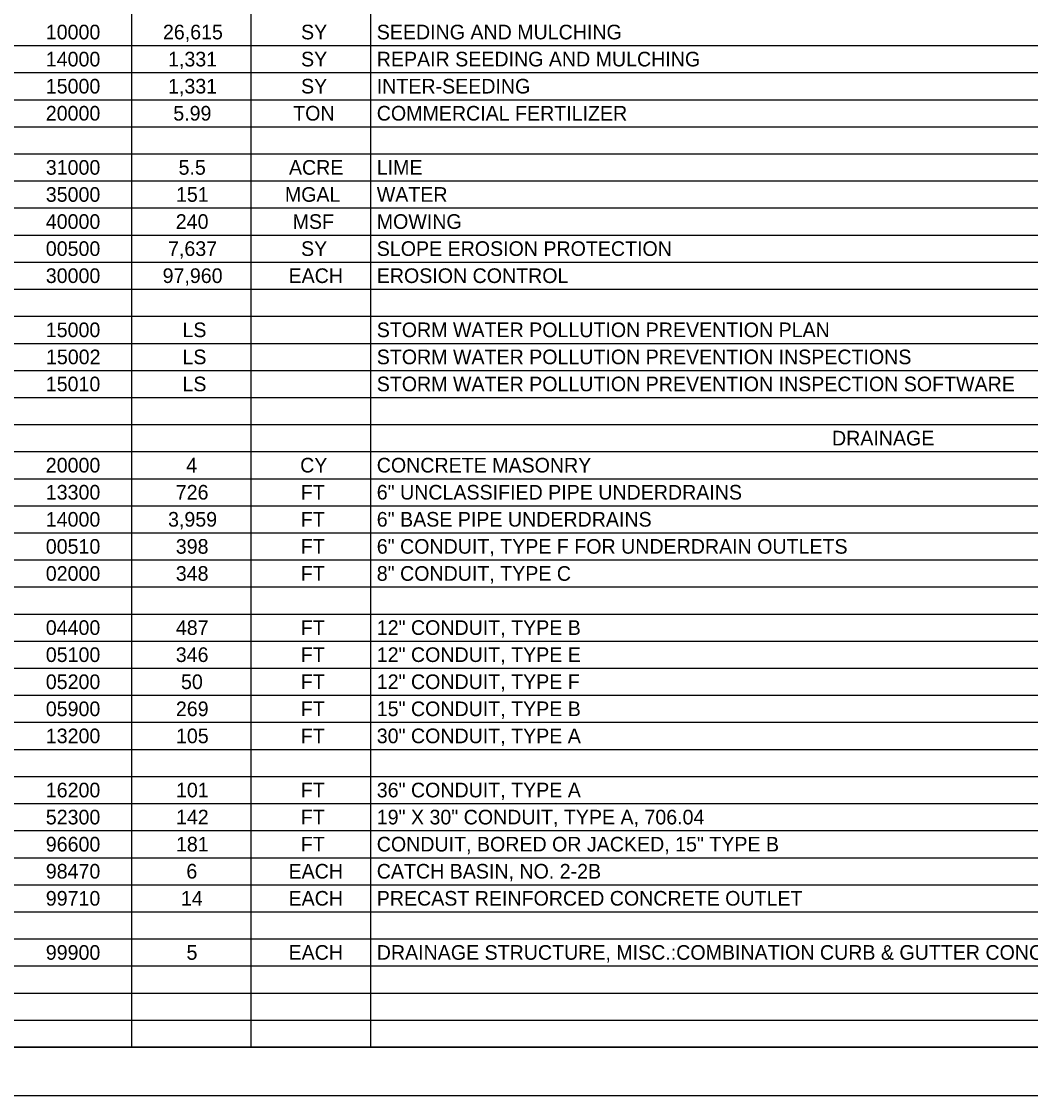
# Model space of a CAD drawing. Extents: x 0 to 34, y 0 to 22.
# Drawn here: x 16.9 to 27.33, y 0 to 11.11 of the extents above; entities that cross this region are included whole.
import ezdxf

# ---------------------------------------------------------------- set-up
doc = ezdxf.new("R2010")
doc.units = 0
for name, color, linetype in [('SH_Border', 7, 'Continuous'), ('SH_Cut_Line', 7, 'Continuous'), ('SH_Text', 7, 'Continuous')]:
    doc.layers.add(name, color=color, linetype=linetype)

msp = doc.modelspace()

# ---------------------------------------------------------------- linework, layer by layer
at = {"layer": 'SH_Border'}
msp.add_lwpolyline([(1.5, 21.5), (33.5, 21.5), (33.5, 0.5), (1.5, 0.5)], close=True, dxfattribs=at)
at = {"layer": 'SH_Cut_Line'}
msp.add_lwpolyline([(0, 0), (34, 0), (34, 22), (0, 22)], close=True, dxfattribs=at)
at = {"layer": 'SH_Text'}
for p, q in [((18.035, 21.5), (18.035, 0.5)), ((19.27, 21.5), (19.27, 0.5)), ((20.505, 21.5), (20.505, 0.5)), ((1.5, 10.86), (32, 10.86)), ((1.5, 10.58), (32, 10.58)), ((1.5, 10.3), (32, 10.3)), ((1.5, 10.02), (32, 10.02)), ((1.5, 9.74), (32, 9.74)), ((1.5, 9.46), (32, 9.46)), ((1.5, 9.18), (32, 9.18)), ((1.5, 8.9), (32, 8.9)), ((1.5, 8.62), (32, 8.62)), ((1.5, 8.34), (32, 8.34)), ((1.5, 8.06), (32, 8.06)), ((1.5, 7.78), (32, 7.78)), ((1.5, 7.5), (32, 7.5)), ((1.5, 7.22), (32, 7.22)), ((1.5, 6.94), (32, 6.94)), ((1.5, 6.66), (32, 6.66)), ((1.5, 6.38), (32, 6.38)), ((1.5, 6.1), (32, 6.1)), ((1.5, 5.82), (32, 5.82)), ((1.5, 5.54), (32, 5.54)), ((1.5, 5.26), (32, 5.26)), ((1.5, 4.98), (32, 4.98)), ((1.5, 4.7), (32, 4.7)), ((1.5, 4.42), (32, 4.42)), ((1.5, 4.14), (32, 4.14)), ((1.5, 3.86), (32, 3.86)), ((1.5, 3.58), (32, 3.58)), ((1.5, 3.3), (32, 3.3)), ((1.5, 3.02), (32, 3.02)), ((1.5, 2.74), (32, 2.74)), ((1.5, 2.46), (32, 2.46)), ((1.5, 2.18), (32, 2.18)), ((1.5, 1.9), (32, 1.9)), ((1.5, 1.62), (32, 1.62)), ((1.5, 1.34), (32, 1.34)), ((1.5, 1.06), (32, 1.06)), ((1.5, 0.78), (32, 0.78)), ((1.5, 0.5), (32, 0.5))]:
    msp.add_line(p, q, dxfattribs=at)

# ---------------------------------------------------------------- texts
for s, height, p in [('10000', 0.1515, (17.149, 10.924)), ('26,615', 0.1515, (18.36, 10.924)), ('SY', 0.1515, (19.788, 10.924)), ('SEEDING AND MULCHING', 0.15153, (20.571, 10.924)), ('14000', 0.1515, (17.149, 10.644)), ('1,331', 0.1515, (18.413, 10.644)), ('SY', 0.1515, (19.788, 10.644)), ('REPAIR SEEDING AND MULCHING', 0.15153, (20.571, 10.644)), ('15000', 0.1515, (17.149, 10.364)), ('1,331', 0.1515, (18.413, 10.364)), ('SY', 0.1515, (19.788, 10.364)), ('INTER-SEEDING', 0.15153, (20.571, 10.364)), ('20000', 0.1515, (17.149, 10.084)), ('5.99', 0.1515, (18.467, 10.084)), ('TON', 0.1515, (19.707, 10.084)), ('COMMERCIAL FERTILIZER', 0.15153, (20.571, 10.084)), ('31000', 0.1515, (17.149, 9.524)), ('5.5', 0.1515, (18.522, 9.524)), ('ACRE', 0.1515, (19.663, 9.524)), ('LIME', 0.1515, (20.571, 9.524)), ('35000', 0.1515, (17.149, 9.244)), ('151', 0.1515, (18.495, 9.244)), ('MGAL', 0.1515, (19.621, 9.244)), ('WATER', 0.1515, (20.571, 9.244)), ('40000', 0.1515, (17.149, 8.964)), ('240', 0.1515, (18.493, 8.964)), ('MSF', 0.1515, (19.701, 8.964)), ('MOWING', 0.1515, (20.571, 8.964)), ('00500', 0.1515, (17.149, 8.684)), ('7,637', 0.1515, (18.413, 8.684)), ('SY', 0.1515, (19.788, 8.684)), ('SLOPE EROSION PROTECTION', 0.15153, (20.571, 8.684)), ('30000', 0.1515, (17.149, 8.404)), ('97,960', 0.1515, (18.357, 8.404)), ('EACH', 0.1515, (19.659, 8.404)), ('EROSION CONTROL', 0.15153, (20.571, 8.404)), ('15000', 0.1515, (17.149, 7.844)), ('LS', 0.1515, (18.562, 7.844)), ('STORM WATER POLLUTION PREVENTION PLAN', 0.15153, (20.571, 7.844)), ('15002', 0.1515, (17.151, 7.564)), ('LS', 0.1515, (18.562, 7.564)), ('STORM WATER POLLUTION PREVENTION INSPECTIONS', 0.15153, (20.571, 7.564)), ('15010', 0.1515, (17.149, 7.284)), ('LS', 0.1515, (18.562, 7.284)), ('STORM WATER POLLUTION PREVENTION INSPECTION SOFTWARE', 0.15153, (20.571, 7.284)), ('DRAINAGE', 0.1515, (25.278, 6.724)), ('20000', 0.1515, (17.149, 6.444)), ('4', 0.152, (18.601, 6.444)), ('CY', 0.1515, (19.779, 6.444)), ('CONCRETE MASONRY', 0.15153, (20.571, 6.444)), ('13300', 0.1515, (17.149, 6.164)), ('726', 0.1515, (18.493, 6.164)), ('FT', 0.1515, (19.786, 6.164)), ('6" UNCLASSIFIED PIPE UNDERDRAINS', 0.15153, (20.571, 6.164)), ('14000', 0.1515, (17.149, 5.884)), ('3,959', 0.1515, (18.413, 5.884)), ('FT', 0.1515, (19.786, 5.884)), ('6" BASE PIPE UNDERDRAINS', 0.15153, (20.571, 5.884)), ('00510', 0.1515, (17.149, 5.604)), ('398', 0.1515, (18.493, 5.604)), ('FT', 0.1515, (19.786, 5.604)), ('6" CONDUIT, TYPE F FOR UNDERDRAIN OUTLETS', 0.15153, (20.571, 5.604)), ('02000', 0.1515, (17.149, 5.324)), ('348', 0.1515, (18.493, 5.324)), ('FT', 0.1515, (19.786, 5.324)), ('8" CONDUIT, TYPE C', 0.15153, (20.571, 5.324)), ('04400', 0.1515, (17.149, 4.764)), ('487', 0.1515, (18.494, 4.764)), ('FT', 0.1515, (19.786, 4.764)), ('12" CONDUIT, TYPE B', 0.15153, (20.571, 4.764)), ('05100', 0.1515, (17.149, 4.484)), ('346', 0.1515, (18.493, 4.484)), ('FT', 0.1515, (19.786, 4.484)), ('12" CONDUIT, TYPE E', 0.15153, (20.571, 4.484)), ('05200', 0.1515, (17.149, 4.204)), ('50', 0.1515, (18.547, 4.204)), ('FT', 0.1515, (19.786, 4.204)), ('12" CONDUIT, TYPE F', 0.15153, (20.571, 4.204)), ('05900', 0.1515, (17.149, 3.924)), ('269', 0.1515, (18.494, 3.924)), ('FT', 0.1515, (19.786, 3.924)), ('15" CONDUIT, TYPE B', 0.15153, (20.571, 3.924)), ('13200', 0.1515, (17.149, 3.644)), ('105', 0.1515, (18.495, 3.644)), ('FT', 0.1515, (19.786, 3.644)), ('30" CONDUIT, TYPE A', 0.15153, (20.571, 3.644)), ('16200', 0.1515, (17.149, 3.084)), ('101', 0.1515, (18.495, 3.084)), ('FT', 0.1515, (19.786, 3.084)), ('36" CONDUIT, TYPE A', 0.15153, (20.571, 3.084)), ('52300', 0.1515, (17.149, 2.804)), ('142', 0.1515, (18.495, 2.804)), ('FT', 0.1515, (19.786, 2.804)), ('19" X 30" CONDUIT, TYPE A, 706.04', 0.15153, (20.571, 2.804)), ('96600', 0.1515, (17.149, 2.524)), ('181', 0.1515, (18.495, 2.524)), ('FT', 0.1515, (19.786, 2.524)), ('CONDUIT, BORED OR JACKED, 15" TYPE B', 0.15153, (20.571, 2.524)), ('98470', 0.1515, (17.149, 2.244)), ('6', 0.152, (18.602, 2.244)), ('EACH', 0.1515, (19.659, 2.244)), ('CATCH BASIN, NO. 2-2B', 0.15153, (20.571, 2.244)), ('99710', 0.1515, (17.149, 1.964)), ('14', 0.1515, (18.546, 1.964)), ('EACH', 0.1515, (19.659, 1.964)), ('PRECAST REINFORCED CONCRETE OUTLET', 0.15153, (20.571, 1.964)), ('99900', 0.1515, (17.149, 1.404)), ('5', 0.152, (18.604, 1.404)), ('EACH', 0.1515, (19.659, 1.404)), ('DRAINAGE STRUCTURE, MISC.:COMBINATION CURB & GUTTER CONCRETE TURNOUT', 0.15153, (20.571, 1.404))]:
    msp.add_text(s, height=height, dxfattribs=at).set_placement(p)

doc.saveas('drawing.dxf')
